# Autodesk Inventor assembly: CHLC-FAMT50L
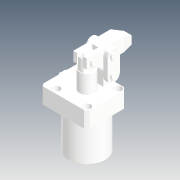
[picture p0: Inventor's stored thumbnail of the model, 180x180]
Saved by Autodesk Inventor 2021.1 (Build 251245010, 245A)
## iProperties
Created: 2019-04
Part Number: CHLC-FAMT50L
Description: STEP AP214
Document SubType Name: Assembly
Designer: user
Title: CHLC-FAMT50L.STEP
Revision Number: ÈÎºÎ
Sending System: SolidWorks 2016
Preprocessor: SwSTEP 2.0
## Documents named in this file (11)
- D:\Vault_2016\Projekty\Clamptek\Hydraulic\CHLC\CHLC-50\Inventor\CHLC-FAMT50L\CHLC-FAMT50L.iam
- D:\Vault_2016\Projekty\Clamptek\Hydraulic\CHLC\CHLC-50\Inventor\CHLC-FAMT50L\CHLC-FAMT50-benti.ipt
- D:\Vault_2016\Projekty\Clamptek\Hydraulic\CHLC\CHLC-50\Inventor\CHLC-FAMT50L\CHLC-50-01.ipt
- D:\Vault_2016\Projekty\Clamptek\Hydraulic\CHLC\CHLC-50\Inventor\CHLC-FAMT50L\CHLC-50-02.ipt
- D:\Vault_2016\Projekty\Clamptek\Hydraulic\CHLC\CHLC-50\Inventor\CHLC-FAMT50L\CHLC-50-04.ipt
- D:\Vault_2016\Projekty\Clamptek\Hydraulic\CHLC\CHLC-50\Inventor\CHLC-FAMT50L\CHLC-50-06.ipt
- D:\Vault_2016\Projekty\Clamptek\Hydraulic\CHLC\CHLC-50\Inventor\CHLC-FAMT50L\CHLC-50-09.ipt
- D:\Vault_2016\Projekty\Clamptek\Hydraulic\CHLC\CHLC-50\Inventor\CHLC-FAMT50L\CZL20µ÷ËÙ·§.iam
- D:\Vault_2016\Projekty\Clamptek\Hydraulic\CHLC\CHLC-50\Inventor\CHLC-FAMT50L\M6LS.ipt
- D:\Vault_2016\Projekty\Clamptek\Hydraulic\CHLC\CHLC-50\Inventor\CHLC-FAMT50L\ZHIC.ipt
- D:\Vault_2016\Projekty\Clamptek\Hydraulic\CHLC\CHLC-50\Inventor\CHLC-FAMT50L\CHLC-50-03.ipt
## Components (19 placed, 19 different names)
1. CHLC-FAMT50-benti_1
2. CHLC-50-01_2
3. CHLC-50-02_3
4. CHLC-50-04_4
5. CHLC-50-06_5
6. CHLC-50-09_6
7. CZL20µ÷ËÙ·§_7 [sub-assembly]
8. M6LS_8
9. ZHIC_9
10. CHLC-50-03_10
11. CHLC-50-03_11
12. CHLC-50-06_12
13. CHLC-50-06_13
14. CHLC-50-06_14
15. CHLC-50-06_15
16. CHLC-50-04_16
17. CHLC-50-06_17
18. M6LS_18
19. M6LS_19
